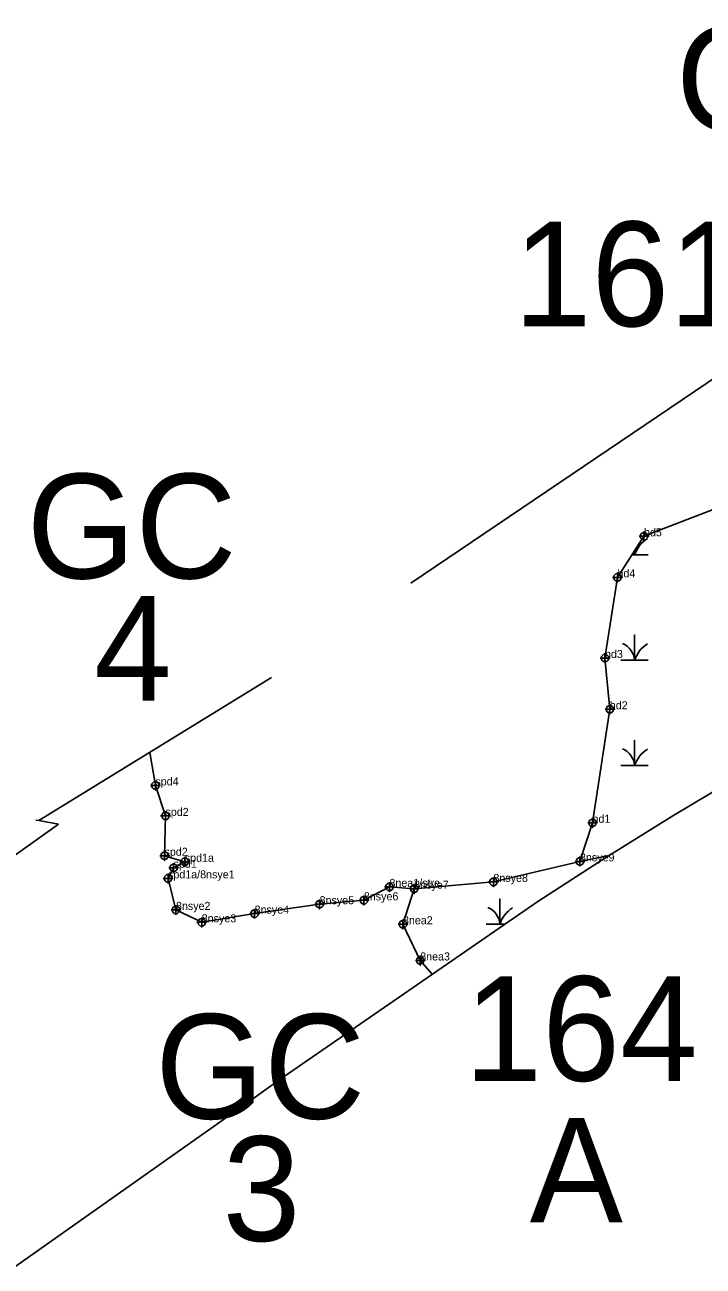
# Model space of a CAD drawing. Extents: x 2071991 to 2268989, y 436479 to 469629.
# Drawn here: x 2183848 to 2184272, y 452453 to 453228 of the extents above; entities that cross this region are included whole.
import ezdxf

# ---------------------------------------------------------------- set-up
doc = ezdxf.new("R2010")
doc.units = 0
for name, color, linetype in [('approx_PSA', 7, 'Continuous'), ('Default', 7, 'Continuous'), ('Exist Environmental Wetland Boundary', 7, 'Continuous'), ('Exist Environmental Wetland Boundary Cogo Comment', 7, 'Continuous'), ('Exist Environmental Wetland Boundary Cogo Point CELL', 7, 'Continuous'), ('Exist Hydro Jurisdictional Stream or Body of Water NEU Mitigable', 7, 'Continuous'), ('Exist Hydro Jurisdictional Stream or Body of Water NEU Mitigable Cogo Comment', 7, 'Continuous'), ('Exist Hydro Jurisdictional Stream or Body of Water NEU Mitigable Cogo Point CELL', 7, 'Continuous'), ('Exist Hydro Swamp or Marsh', 7, 'Continuous')]:
    doc.layers.add(name, color=color, linetype=linetype)

msp = doc.modelspace()

# ---------------------------------------------------------------- linework, layer by layer
at = {"layer": 'approx_PSA'}
for p, q in [((2184089.6, 452879.29), (2184290.42, 453015.15)), ((2184089.6, 452879.29), (2184089.6, 452879.29)), ((2184089.6, 452879.29), (2184089.6, 452879.29)), ((2183982.66, 452808.17), (2184002.65, 452820.47)), ((2184002.65, 452820.47), (2184002.65, 452820.47)), ((2184002.65, 452820.47), (2184002.65, 452820.47)), ((2184002.65, 452820.47), (2184002.65, 452820.47)), ((2184002.65, 452820.47), (2184002.65, 452820.47)), ((2184002.65, 452820.47), (2184002.65, 452820.47)), ((2184002.65, 452820.47), (2184002.65, 452820.47)), ((2184002.65, 452820.47), (2184002.65, 452820.47)), ((2184002.65, 452820.47), (2184002.65, 452820.47)), ((2184002.65, 452820.47), (2184002.65, 452820.47)), ((2184002.65, 452820.47), (2184002.65, 452820.47)), ((2184002.65, 452820.47), (2184002.65, 452820.47)), ((2184002.65, 452820.47), (2184002.65, 452820.47)), ((2184002.65, 452820.47), (2184002.65, 452820.47)), ((2184002.65, 452820.47), (2184002.65, 452820.47)), ((2184002.65, 452820.47), (2184002.65, 452820.47)), ((2184002.65, 452820.47), (2184002.65, 452820.47)), ((2184002.65, 452820.47), (2184002.65, 452820.47)), ((2184002.65, 452820.47), (2184002.65, 452820.47)), ((2184002.65, 452820.47), (2184002.65, 452820.47)), ((2184002.65, 452820.47), (2184002.65, 452820.47)), ((2184002.65, 452820.47), (2184002.65, 452820.47)), ((2184002.65, 452820.47), (2184002.65, 452820.47)), ((2184002.65, 452820.47), (2184002.65, 452820.47)), ((2184002.65, 452820.47), (2184002.65, 452820.47)), ((2184002.65, 452820.47), (2184002.65, 452820.47)), ((2184002.65, 452820.47), (2184002.65, 452820.47)), ((2184002.65, 452820.47), (2184002.65, 452820.47)), ((2184002.65, 452820.47), (2184002.65, 452820.47)), ((2184002.65, 452820.47), (2184002.65, 452820.47)), ((2184002.65, 452820.47), (2184002.65, 452820.47)), ((2184002.65, 452820.47), (2184002.65, 452820.47)), ((2184002.65, 452820.47), (2184002.65, 452820.47)), ((2184002.65, 452820.47), (2184002.65, 452820.47)), ((2184002.65, 452820.47), (2184002.65, 452820.47)), ((2184002.65, 452820.47), (2184002.65, 452820.47)), ((2184002.65, 452820.47), (2184002.65, 452820.47)), ((2184002.65, 452820.47), (2184002.65, 452820.47)), ((2184002.65, 452820.47), (2184002.65, 452820.47)), ((2184002.65, 452820.47), (2184002.65, 452820.47)), ((2184002.65, 452820.47), (2184002.65, 452820.47)), ((2184002.65, 452820.47), (2184002.65, 452820.47)), ((2183857.26, 452731.01), (2183982.66, 452808.17)), ((2184291.09, 452756.53), (2184253.23, 452733.93)), ((2183721.68, 452624.16), (2183869.6, 452728.77)), ((2183857.26, 452731.01), (2183855.4, 452731.35)), ((2183855.4, 452731.35), (2183855.4, 452731.35)), ((2183855.4, 452731.35), (2183857.26, 452731.01)), ((2183869.6, 452728.77), (2183857.26, 452731.01)), ((2184253.23, 452733.93), (2184210.83, 452707.6)), ((2184210.83, 452707.6), (2184168.89, 452680.54)), ((2184168.89, 452680.54), (2184007.11, 452568.81)), ((2184007.11, 452568.81), (2183990.86, 452557.32)), ((2183990.86, 452557.32), (2183842.94, 452452.71))]:
    msp.add_line(p, q, dxfattribs=at)
at = {"layer": 'Exist Environmental Wetland Boundary'}
for points in [[(2184342.64, 452954.22), (2184377.49, 452907.7), (2184351.26, 452889.03), (2184340.31, 452898.72), (2184318.51, 452907.5), (2184305.63, 452919.59), (2184281.2, 452926.35), (2184235.29, 452908.62), (2184218.7, 452882.98), (2184210.93, 452832.58), (2184213.95, 452800.56), (2184203.13, 452729.67), (2184195.27, 452705.58)], [(2184091.73, 452688.49), (2184084.71, 452666.29), (2184095.48, 452643.67), (2184102.96, 452635.01)]]:
    msp.add_lwpolyline(points, dxfattribs=at)
at = {"layer": 'Exist Environmental Wetland Boundary Cogo Point CELL'}
for points in [[(2184235.29, 452911.62), (2184235.29, 452905.62), (2184235.29, 452908.62), (2184238.29, 452908.62), (2184232.29, 452908.62)], [(2184218.7, 452885.98), (2184218.7, 452879.98), (2184218.7, 452882.98), (2184221.7, 452882.98), (2184215.7, 452882.98)], [(2184210.93, 452835.58), (2184210.93, 452829.58), (2184210.93, 452832.58), (2184213.93, 452832.58), (2184207.93, 452832.58)], [(2184213.95, 452803.56), (2184213.95, 452797.56), (2184213.95, 452800.56), (2184216.95, 452800.56), (2184210.95, 452800.56)], [(2184203.13, 452732.67), (2184203.13, 452726.67), (2184203.13, 452729.67), (2184206.13, 452729.67), (2184200.13, 452729.67)], [(2184084.71, 452669.29), (2184084.71, 452663.29), (2184084.71, 452666.29), (2184087.71, 452666.29), (2184081.71, 452666.29)], [(2184095.48, 452646.67), (2184095.48, 452640.67), (2184095.48, 452643.67), (2184098.48, 452643.67), (2184092.48, 452643.67)]]:
    msp.add_lwpolyline(points, dxfattribs=at)
for centre in [(2184235.29, 452908.62), (2184218.7, 452882.98), (2184210.93, 452832.58), (2184213.95, 452800.56), (2184203.13, 452729.67), (2184084.71, 452666.29), (2184095.48, 452643.67)]:
    msp.add_circle(centre, 2.34, dxfattribs=at)
at = {"layer": 'Exist Hydro Jurisdictional Stream or Body of Water NEU Mitigable'}
for points in [[(2183926.6, 452773.68), (2183930.04, 452753.02), (2183936.35, 452733.98), (2183935.77, 452709.08), (2183948.4, 452705.32), (2183941.42, 452701.55)], [(2184213.55, 452709.3), (2184195.27, 452705.58), (2184141.22, 452692.72), (2184091.73, 452688.49)], [(2183941.42, 452701.55), (2183937.94, 452694.94), (2183942.91, 452675.26), (2183959.02, 452667.5), (2183992.04, 452672.94), (2184032.66, 452678.81), (2184060.31, 452681.25), (2184076.27, 452689.62), (2184091.73, 452688.49)]]:
    msp.add_lwpolyline(points, dxfattribs=at)
at = {"layer": 'Exist Hydro Jurisdictional Stream or Body of Water NEU Mitigable Cogo Point CELL'}
for points in [[(2183930.04, 452756.02), (2183930.04, 452750.02), (2183930.04, 452753.02), (2183933.04, 452753.02), (2183927.04, 452753.02)], [(2183936.35, 452736.98), (2183936.35, 452730.98), (2183936.35, 452733.98), (2183939.35, 452733.98), (2183933.35, 452733.98)], [(2183935.77, 452712.08), (2183935.77, 452706.08), (2183935.77, 452709.08), (2183938.77, 452709.08), (2183932.77, 452709.08)], [(2183941.42, 452704.55), (2183941.42, 452698.55), (2183941.42, 452701.55), (2183944.42, 452701.55), (2183938.42, 452701.55)], [(2183948.4, 452708.32), (2183948.4, 452702.32), (2183948.4, 452705.32), (2183951.4, 452705.32), (2183945.4, 452705.32)], [(2184195.27, 452708.58), (2184195.27, 452702.58), (2184195.27, 452705.58), (2184198.27, 452705.58), (2184192.27, 452705.58)], [(2183937.94, 452697.94), (2183937.94, 452691.94), (2183937.94, 452694.94), (2183940.94, 452694.94), (2183934.94, 452694.94)], [(2184076.27, 452692.62), (2184076.27, 452686.62), (2184076.27, 452689.62), (2184079.27, 452689.62), (2184073.27, 452689.62)], [(2184091.73, 452691.49), (2184091.73, 452685.49), (2184091.73, 452688.49), (2184094.73, 452688.49), (2184088.73, 452688.49)], [(2184141.22, 452695.72), (2184141.22, 452689.72), (2184141.22, 452692.72), (2184144.22, 452692.72), (2184138.22, 452692.72)], [(2184032.66, 452681.81), (2184032.66, 452675.81), (2184032.66, 452678.81), (2184035.66, 452678.81), (2184029.66, 452678.81)], [(2184060.31, 452684.25), (2184060.31, 452678.25), (2184060.31, 452681.25), (2184063.31, 452681.25), (2184057.31, 452681.25)], [(2183942.91, 452678.26), (2183942.91, 452672.26), (2183942.91, 452675.26), (2183945.91, 452675.26), (2183939.91, 452675.26)], [(2183992.04, 452675.94), (2183992.04, 452669.94), (2183992.04, 452672.94), (2183995.04, 452672.94), (2183989.04, 452672.94)], [(2183959.02, 452670.5), (2183959.02, 452664.5), (2183959.02, 452667.5), (2183962.02, 452667.5), (2183956.02, 452667.5)]]:
    msp.add_lwpolyline(points, dxfattribs=at)
for centre in [(2183930.04, 452753.02), (2183936.35, 452733.98), (2183935.77, 452709.08), (2183948.4, 452705.32), (2184195.27, 452705.58), (2183937.94, 452694.94), (2183941.42, 452701.55), (2184076.27, 452689.62), (2184091.73, 452688.49), (2184141.22, 452692.72), (2184032.66, 452678.81), (2184060.31, 452681.25), (2183942.91, 452675.26), (2183992.04, 452672.94), (2183959.02, 452667.5)]:
    msp.add_circle(centre, 2.34, dxfattribs=at)
at = {"layer": 'Exist Hydro Swamp or Marsh'}
msp.add_line((2184084.72, 452666.34), (2184086.62, 452666.34), dxfattribs=at)
for points in [[(2184227.78, 452897.01), (2184229.39, 452897.01), (2184229.39, 452899.51)], [(2184229.39, 452899.51), (2184229.39, 452897.01), (2184238, 452897.01)], [(2184220.79, 452831.22), (2184229.39, 452831.22), (2184229.39, 452847.01), (2184229.39, 452831.22), (2184238, 452831.22)], [(2184220.79, 452765.44), (2184229.39, 452765.44), (2184229.39, 452781.22), (2184229.39, 452765.44), (2184238, 452765.44)], [(2184136.62, 452666.34), (2184145.22, 452666.34), (2184145.22, 452682.13), (2184145.22, 452666.34), (2184148.33, 452666.34)]]:
    msp.add_lwpolyline(points, dxfattribs=at)
for centre, radius, start, end in [((2184247.64, 452890.94), 19.22, 122.12745, 161.62219), ((2184217.13, 452896.12), 12.3, 4.14034, 13.64857), ((2184217.13, 452830.34), 12.3, 4.14034, 67.53497), ((2184247.64, 452825.16), 19.22, 122.12745, 161.62219), ((2184217.13, 452764.56), 12.3, 4.14034, 67.53497), ((2184247.64, 452759.38), 19.22, 122.12745, 161.62219), ((2184132.96, 452665.46), 12.3, 4.14034, 67.53497), ((2184163.47, 452660.28), 19.22, 122.12745, 161.62219)]:
    msp.add_arc(centre, radius, start, end, dxfattribs=at)

# ---------------------------------------------------------------- texts
at = {"layer": 'Default'}
for s, p in [('GC', (2184255.25, 453161.81)), ('161', (2184153.82, 453039.86)), ('GC', (2183849.66, 452882.32)), ('4', (2183891.73, 452805.99)), ('164', (2184123.11, 452568.48)), ('GC', (2183930.01, 452544.81)), ('A', (2184163.86, 452479.99)), ('3', (2183972.08, 452468.47))]:
    msp.add_text(s, height=65.34, dxfattribs=at).set_placement(p)
at = {"layer": 'Exist Environmental Wetland Boundary Cogo Comment'}
for s, p in [('hd5', (2184235.29, 452908.62)), ('hd4', (2184218.7, 452882.98)), ('hd3', (2184210.93, 452832.58)), ('hd2', (2184213.95, 452800.56)), ('hd1', (2184203.13, 452729.67)), ('8nea2', (2184084.71, 452666.29)), ('8nea3', (2184095.48, 452643.67))]:
    msp.add_text(s, height=5, dxfattribs=at).set_placement(p)
at = {"layer": 'Exist Hydro Jurisdictional Stream or Body of Water NEU Mitigable Cogo Comment'}
for s, p in [('spd4', (2183930.04, 452753.02)), ('spd2', (2183936.35, 452733.98)), ('spd2', (2183935.77, 452709.08)), ('spd1', (2183941.42, 452701.55)), ('spd1a', (2183948.4, 452705.32)), ('8nsye9', (2184195.27, 452705.58)), ('spd1a/8nsye1', (2183937.94, 452694.94)), ('8nsye8', (2184141.22, 452692.72)), ('8nea1/stre', (2184076.27, 452689.62)), ('8nsye7', (2184091.73, 452688.49)), ('8nsye5', (2184032.66, 452678.81)), ('8nsye6', (2184060.31, 452681.25)), ('8nsye2', (2183942.91, 452675.26)), ('8nsye4', (2183992.04, 452672.94)), ('8nsye3', (2183959.02, 452667.5))]:
    msp.add_text(s, height=5, dxfattribs=at).set_placement(p)

doc.saveas('drawing.dxf')
